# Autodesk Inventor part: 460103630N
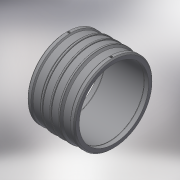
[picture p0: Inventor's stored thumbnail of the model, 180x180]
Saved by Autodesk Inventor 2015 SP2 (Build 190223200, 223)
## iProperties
Created: 2017-06
Part Number: 460103630N
Material: Generic
Description: PLASSON LIGHTFIT COUPLER 630N
Document SubType Name: Modeling
Designer: KIM
Mass: 23460.8 g
Surface Area: 18605.1 cm^2
Volume: 23460.8 cm^3
Density: 1 g/cm^3
Appearance: Default
Author: KIM
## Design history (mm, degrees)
derived "460103.ipt"
feature "Solid1::460103.ipt"
tag "TaggingFeature1"
body "Solid1"
other parameters: "d14" = 17.6296, "d19" = 3.52592, "d20" = 168 deg, "d22" = 693, "d23" = 706, "d24" = 672.21, "d25" = 135 deg, "d27" = 135 deg, "d29" = 346.5, "d35" = 15, "d39" = 0, "d40" = 4, "d41" = 14, "d42" = 0, "d43" = 135 deg, "d44" = 44, "d45" = 16, "d46" = 16, "d47" = 16, "d48" = 691.88, "d49" = 706, "d50" = 3.53, "d51" = 6, "d52" = 0, "D_" = 706, "A_" = 346.5, "d_2" = 12
